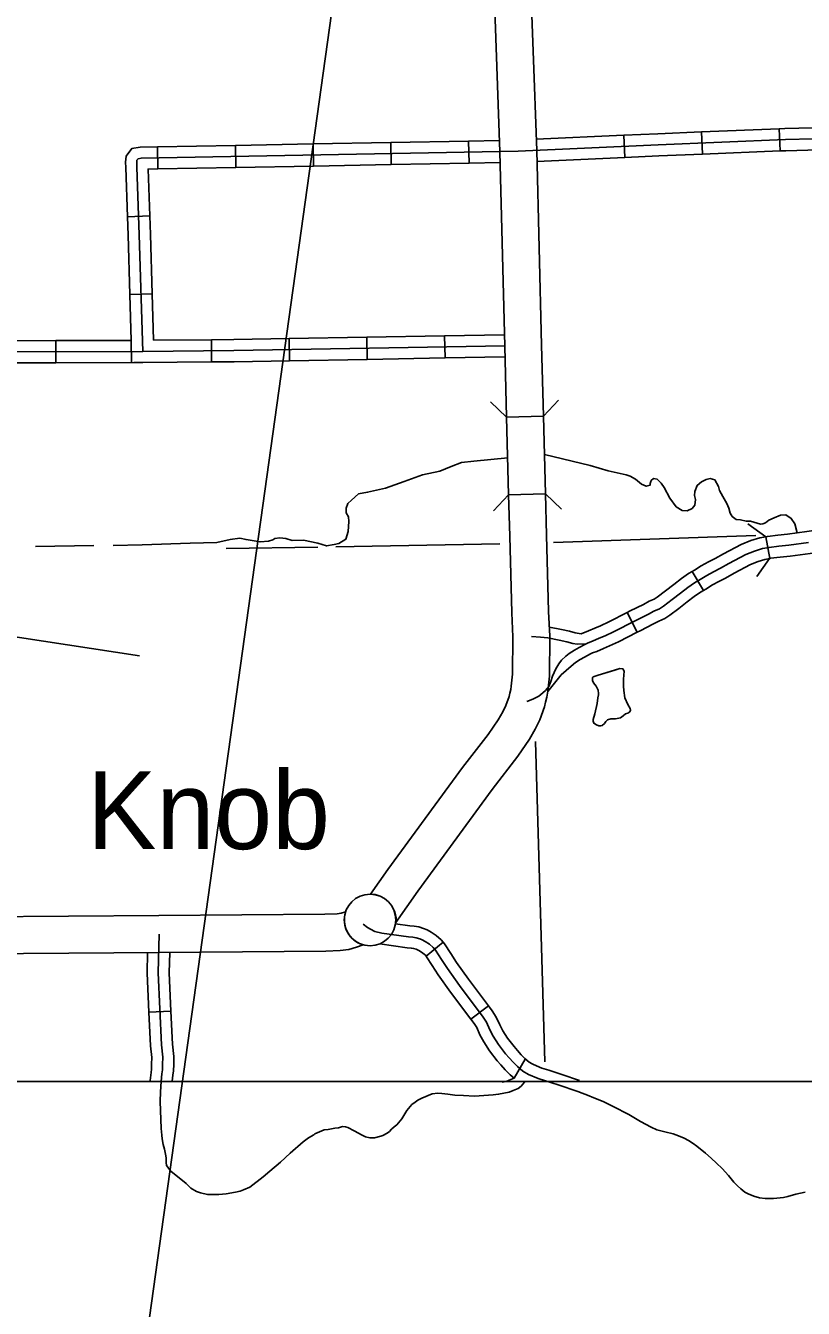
# Model space of a CAD drawing. Extents: x -5566 to 1759129, y -3726 to 731467.
# Drawn here: x -4832.8 to -4792.7, y 148.8 to 214.9 of the extents above; entities that cross this region are included whole.
import ezdxf

# ---------------------------------------------------------------- set-up
doc = ezdxf.new("R2010")
doc.units = 0
doc.layers.add('Default', color=7, linetype='Continuous')
doc.layers.add('R_No Plot', color=7, linetype='Continuous')

msp = doc.modelspace()

# ---------------------------------------------------------------- linework, layer by layer
at = {"layer": 'Default'}
for p, q in [((-4793.957, 209.609), (-4793.912, 208.471)), ((-4813.98, 208.907), (-4813.959, 207.768)), ((-4809.971, 208.982), (-4809.95, 207.843)), ((-4801.973, 209.278), (-4801.921, 208.14)), ((-4797.964, 209.449), (-4797.918, 208.31)), ((-4826.007, 208.68), (-4825.986, 207.542)), ((-4821.998, 208.756), (-4821.977, 207.617)), ((-4817.989, 208.831), (-4817.968, 207.693)), ((-4827.552, 205.078), (-4826.414, 205.118)), ((-4827.43, 201.073), (-4826.291, 201.106)), ((-4831.244, 197.558), (-4831.247, 198.697)), ((-4827.358, 197.569), (-4827.361, 198.708)), ((-4823.221, 197.598), (-4823.23, 198.737)), ((-4819.206, 197.658), (-4819.227, 198.797)), ((-4815.197, 197.729), (-4815.218, 198.868)), ((-4811.188, 197.8), (-4811.208, 198.939)), ((-4794.659, 188.587), (-4794.454, 187.466)), ((-4798.451, 186.793), (-4797.859, 185.82)), ((-4801.796, 184.688), (-4801.277, 183.674)), ((-4812.166, 166.969), (-4811.288, 167.693)), ((-4826.453, 164.078), (-4825.315, 164.129)), ((-4809.86, 163.724), (-4808.948, 164.407)), ((-4807.633, 160.687), (-4807.051, 161.666))]:
    msp.add_line(p, q, dxfattribs=at)
for points in [[(-4808.611, 250.608), (-4808.503, 248.641), (-4807.793, 238.866), (-4807.024, 228.557), (-4806.829, 218.746), (-4806.464, 208.49), (-4806.212, 198.466), (-4806.116, 194.8)], [(-4806.116, 194.8), (-4808.014, 194.75), (-4808.11, 198.417), (-4808.362, 208.432), (-4808.727, 218.693), (-4808.921, 228.467), (-4809.687, 238.726), (-4810.398, 248.52), (-4810.507, 250.505)], [(-4829.868, 123.724), (-4829.868, 123.724), (-4813.198, 243.138)], [(-4787.797, 217.644), (-4787.592, 212.789), (-4787.515, 210.186), (-4787.571, 210.105), (-4787.69, 210.011), (-4788.167, 209.811), (-4788.634, 209.538), (-4789.008, 209.375), (-4789.249, 209.291), (-4789.461, 209.239), (-4789.684, 209.188), (-4790.113, 209.159), (-4790.784, 209.13), (-4793.645, 209.052), (-4800.199, 208.789), (-4807.413, 208.461), (-4826.849, 208.095), (-4827.014, 208.066), (-4827.072, 207.988), (-4827.082, 207.881), (-4827.072, 207.637), (-4826.949, 204.144), (-4826.775, 198.14)], [(-4793.957, 209.609), (-4797.964, 209.449)], [(-4789.966, 209.74), (-4790.144, 209.728), (-4790.804, 209.699), (-4793.664, 209.621), (-4793.957, 209.609)], [(-4813.98, 208.907), (-4817.989, 208.831)], [(-4809.971, 208.982), (-4813.98, 208.907)], [(-4808.382, 209.012), (-4809.971, 208.982)], [(-4801.973, 209.278), (-4806.485, 209.073)], [(-4797.964, 209.449), (-4800.223, 209.358), (-4801.973, 209.278)], [(-4826.007, 208.68), (-4826.904, 208.664), (-4827.335, 208.588), (-4827.625, 208.2), (-4827.653, 207.895), (-4827.642, 207.616), (-4827.552, 205.078)], [(-4821.998, 208.756), (-4826.007, 208.68)], [(-4817.989, 208.831), (-4821.998, 208.756)], [(-4797.918, 208.31), (-4800.174, 208.22), (-4801.921, 208.14)], [(-4793.912, 208.471), (-4797.918, 208.31)], [(-4789.888, 208.603), (-4790.081, 208.59), (-4790.764, 208.56), (-4793.625, 208.483), (-4793.912, 208.471)], [(-4821.977, 207.617), (-4825.986, 207.542)], [(-4817.968, 207.693), (-4821.977, 207.617)], [(-4813.959, 207.768), (-4817.968, 207.693)], [(-4809.95, 207.843), (-4813.959, 207.768)], [(-4808.348, 207.874), (-4809.95, 207.843)], [(-4801.921, 208.14), (-4806.45, 207.935)], [(-4825.986, 207.542), (-4826.499, 207.532), (-4826.414, 205.118)], [(-4827.552, 205.078), (-4827.519, 204.126), (-4827.43, 201.073)], [(-4826.414, 205.118), (-4826.38, 204.162), (-4826.291, 201.106)], [(-4827.43, 201.073), (-4827.361, 198.708)], [(-4826.291, 201.106), (-4826.222, 198.714)], [(-4811.208, 198.939), (-4808.12, 198.994)], [(-4846.324, 187.972), (-4846.526, 195.499), (-4846.607, 197.275), (-4846.615, 197.587), (-4846.607, 197.735), (-4846.548, 197.839), (-4846.429, 197.906), (-4846.261, 197.925), (-4846.033, 197.944), (-4843.755, 197.958), (-4833.845, 198.12), (-4826.775, 198.14), (-4822.075, 198.177), (-4808.11, 198.424)], [(-4835.264, 198.667), (-4833.851, 198.69), (-4831.247, 198.697)], [(-4831.247, 198.697), (-4827.361, 198.708)], [(-4826.222, 198.714), (-4823.23, 198.737)], [(-4823.23, 198.737), (-4822.082, 198.746), (-4819.227, 198.797)], [(-4819.227, 198.797), (-4815.218, 198.868)], [(-4815.218, 198.868), (-4811.208, 198.939)], [(-4819.206, 197.658), (-4815.197, 197.729)], [(-4815.197, 197.729), (-4811.188, 197.8)], [(-4811.188, 197.8), (-4808.1, 197.855)], [(-4835.245, 197.528), (-4833.84, 197.551), (-4831.244, 197.558)], [(-4831.244, 197.558), (-4827.234, 197.57)], [(-4827.234, 197.57), (-4826.772, 197.571), (-4823.221, 197.598)], [(-4823.221, 197.598), (-4822.067, 197.607), (-4819.206, 197.658)], [(-4808.014, 194.75), (-4808.84, 195.535)], [(-4805.332, 195.627), (-4806.116, 194.8)], [(-4808.014, 194.75), (-4807.909, 190.743)], [(-4806.116, 194.8), (-4806.011, 190.793)], [(-4826.794, 188.163), (-4824.32, 188.261), (-4822.958, 188.288), (-4822.263, 188.441), (-4821.763, 188.511), (-4821.443, 188.441), (-4820.72, 188.316), (-4820.29, 188.358), (-4820.072, 188.433), (-4819.961, 188.499), (-4819.704, 188.527), (-4819.399, 188.496), (-4819.074, 188.4), (-4818.49, 188.414), (-4817.753, 188.261), (-4817.296, 188.11), (-4816.906, 188.191), (-4816.667, 188.242), (-4816.294, 188.455), (-4816.183, 188.858), (-4816.141, 189.373), (-4816.169, 189.609), (-4816.278, 189.815), (-4816.282, 190.064), (-4816.197, 190.304), (-4816.002, 190.471), (-4815.653, 190.795), (-4815.179, 190.879), (-4814.251, 191.089), (-4813.302, 191.432), (-4812.347, 191.778), (-4811.464, 191.973), (-4810.868, 192.215), (-4810.337, 192.409), (-4809.702, 192.478), (-4807.959, 192.66)], [(-4806.064, 192.831), (-4803.706, 192.265), (-4802.772, 191.99), (-4801.849, 191.775), (-4801.641, 191.717), (-4801.375, 191.562), (-4801.058, 191.295), (-4800.817, 191.192), (-4800.607, 191.248), (-4800.611, 191.331), (-4800.565, 191.479), (-4800.449, 191.584), (-4800.257, 191.555), (-4800.049, 191.351), (-4799.886, 191.13), (-4799.593, 190.579), (-4799.267, 190.13), (-4798.961, 189.931), (-4798.702, 189.92), (-4798.457, 190.047), (-4798.306, 190.222), (-4798.282, 190.498), (-4798.33, 190.717), (-4798.318, 190.924), (-4798.188, 191.228), (-4797.969, 191.414), (-4797.724, 191.533), (-4797.521, 191.581), (-4797.283, 191.524), (-4797.098, 191.174), (-4797.035, 190.978), (-4796.86, 190.666), (-4796.668, 190.301), (-4796.557, 190.063), (-4796.498, 189.798), (-4796.384, 189.636), (-4796.186, 189.47), (-4795.951, 189.455), (-4795.674, 189.392), (-4795.441, 189.395), (-4794.922, 189.238), (-4794.812, 189.254), (-4794.663, 189.301), (-4794.489, 189.438), (-4794.229, 189.565), (-4793.892, 189.694), (-4793.617, 189.71), (-4793.344, 189.53), (-4793.158, 189.257), (-4793.031, 188.784)], [(-4826.935, 182.452), (-4843.256, 184.94), (-4846.227, 185.456), (-4848.789, 185.805), (-4851.152, 186.181), (-4852.083, 186.359), (-4856.427, 186.982), (-4862.755, 188.176), (-4869.158, 189.202), (-4878.205, 190.691)], [(-4815.029, 170.165), (-4814.798, 170.147), (-4814.539, 170.064), (-4814.304, 169.944), (-4814.106, 169.773), (-4813.93, 169.557), (-4813.783, 169.261), (-4813.709, 168.952), (-4813.731, 168.71), (-4812.597, 170.324), (-4808.766, 175.557), (-4807.431, 177.283), (-4806.841, 178.146), (-4806.543, 178.666), (-4806.297, 179.15), (-4806.066, 179.82), (-4806.007, 180.061), (-4805.942, 180.312), (-4805.888, 180.631), (-4805.812, 181.402), (-4805.787, 183.454), (-4805.849, 184.742), (-4805.955, 188.671), (-4806.011, 190.793), (-4807.909, 190.743)], [(-4807.909, 190.743), (-4807.853, 188.62), (-4807.747, 184.67), (-4807.686, 183.42), (-4807.71, 181.508), (-4807.771, 180.881), (-4807.8, 180.708), (-4807.848, 180.526), (-4807.889, 180.356), (-4808.049, 179.893), (-4808.213, 179.569), (-4808.45, 179.156), (-4808.967, 178.401), (-4810.283, 176.698), (-4814.14, 171.43), (-4815.029, 170.165)], [(-4808.693, 189.917), (-4807.909, 190.743)], [(-4806.011, 190.793), (-4805.185, 190.009)], [(-4795.585, 189.244), (-4794.654, 188.587)], [(-4790.762, 189.316), (-4791.007, 189.258), (-4791.606, 189.074), (-4791.958, 188.94), (-4792.536, 188.849), (-4793.535, 188.717), (-4794.036, 188.668), (-4794.574, 188.602), (-4794.659, 188.587)], [(-4805.604, 188.283), (-4795.164, 188.652)], [(-4794.659, 188.587), (-4794.969, 188.53), (-4795.429, 188.385), (-4795.926, 188.191), (-4796.84, 187.7), (-4797.262, 187.462), (-4797.609, 187.285), (-4797.978, 187.088), (-4798.337, 186.862), (-4798.451, 186.793)], [(-4829.3, 188.129), (-4832.307, 188.088)], [(-4826.794, 188.163), (-4828.297, 188.143)], [(-4822.477, 187.98), (-4817.751, 188.058)], [(-4816.824, 188.074), (-4808.362, 188.215)], [(-4792.455, 188.286), (-4793.47, 188.151), (-4793.974, 188.101), (-4794.488, 188.039), (-4794.832, 187.976), (-4795.24, 187.848), (-4795.687, 187.673), (-4796.565, 187.201), (-4796.992, 186.96), (-4797.345, 186.78), (-4797.692, 186.595), (-4798.038, 186.378), (-4798.323, 186.204), (-4798.67, 185.969), (-4799.054, 185.678), (-4799.481, 185.344), (-4799.926, 185.015), (-4800.137, 184.873), (-4800.422, 184.749), (-4800.7, 184.595), (-4801.394, 184.254), (-4802.496, 183.69), (-4802.941, 183.48), (-4803.238, 183.356), (-4803.579, 183.207), (-4803.812, 183.119), (-4803.95, 183.052), (-4804.266, 182.885), (-4804.508, 182.749), (-4804.792, 182.569), (-4804.967, 182.428), (-4805.182, 182.223), (-4805.322, 182.044), (-4805.484, 181.776), (-4805.653, 181.407), (-4805.739, 181.122), (-4805.845, 180.875), (-4806.006, 180.668), (-4806.148, 180.544), (-4806.352, 180.365), (-4806.656, 180.224), (-4806.978, 180.088)], [(-4790.499, 188.208), (-4790.707, 188.158), (-4791.235, 187.996), (-4791.664, 187.832), (-4792.373, 187.722), (-4793.404, 187.585), (-4793.912, 187.535), (-4794.403, 187.475), (-4794.454, 187.466)], [(-4794.454, 187.466), (-4794.695, 187.422), (-4795.051, 187.31), (-4795.448, 187.155), (-4796.29, 186.703), (-4796.723, 186.458), (-4797.081, 186.275), (-4797.406, 186.101), (-4797.739, 185.893), (-4797.859, 185.82)], [(-4794.459, 187.465), (-4795.115, 186.534)], [(-4798.451, 186.793), (-4798.631, 186.684), (-4799.002, 186.432), (-4799.401, 186.129), (-4799.825, 185.797), (-4800.255, 185.481), (-4800.413, 185.374), (-4800.674, 185.26), (-4800.964, 185.1), (-4801.649, 184.763), (-4801.796, 184.688)], [(-4797.859, 185.82), (-4798.015, 185.725), (-4798.338, 185.506), (-4798.706, 185.227), (-4799.136, 184.89), (-4799.598, 184.55), (-4799.861, 184.372), (-4800.17, 184.238), (-4800.437, 184.09), (-4801.138, 183.745), (-4801.277, 183.674)], [(-4801.796, 184.688), (-4802.747, 184.201), (-4803.172, 184.001), (-4803.462, 183.88), (-4803.794, 183.734), (-4804.177, 183.589)], [(-4804.177, 183.589), (-4804.482, 183.64), (-4804.78, 183.724), (-4805.186, 183.809), (-4805.81, 183.934)], [(-4803.933, 183.061), (-4804.384, 183.046), (-4804.607, 183.083), (-4804.916, 183.17), (-4805.3, 183.251), (-4805.888, 183.369), (-4806.266, 183.406), (-4806.736, 183.437)], [(-4801.277, 183.674), (-4802.244, 183.179), (-4802.71, 182.959), (-4803.015, 182.832), (-4803.363, 182.68), (-4803.587, 182.595), (-4803.694, 182.544), (-4803.993, 182.385), (-4804.215, 182.26), (-4804.46, 182.105), (-4804.681, 181.914)], [(-4804.681, 181.914), (-4805.201, 181.464), (-4805.89, 180.617)], [(-4803.311, 180.277), (-4803.286, 180.445), (-4803.274, 180.5), (-4803.298, 180.686), (-4803.404, 180.878), (-4803.527, 181.064), (-4803.589, 181.175), (-4803.589, 181.25), (-4803.583, 181.33), (-4803.546, 181.374), (-4803.298, 181.448), (-4802.444, 181.708), (-4802.178, 181.788), (-4802.023, 181.776), (-4801.961, 181.652), (-4801.986, 181.25), (-4801.992, 180.891), (-4801.974, 180.661)], [(-4803.546, 181.374), (-4803.298, 181.448), (-4802.178, 181.788)], [(-4801.974, 180.661), (-4801.924, 180.284), (-4801.769, 179.943), (-4801.639, 179.732), (-4801.621, 179.646), (-4801.67, 179.571), (-4801.763, 179.491), (-4801.881, 179.46), (-4802.011, 179.361), (-4802.147, 179.249), (-4802.401, 179.206), (-4802.648, 179.2), (-4802.809, 179.144), (-4802.902, 179.057), (-4802.97, 178.965), (-4803.094, 178.859), (-4803.162, 178.841), (-4803.255, 178.841), (-4803.373, 178.89), (-4803.515, 178.977), (-4803.558, 179.082), (-4803.552, 179.163), (-4803.465, 179.454), (-4803.354, 179.986), (-4803.311, 180.277)], [(-4806.042, 161.524), (-4806.518, 178.041)], [(-4815.415, 167.558), (-4815.683, 167.665), (-4815.891, 167.803), (-4816.066, 167.974), (-4816.223, 168.205), (-4816.32, 168.431), (-4816.375, 168.721), (-4816.37, 168.998), (-4816.316, 169.252), (-4816.542, 169.184), (-4816.749, 169.158), (-4817.38, 169.132), (-4825.946, 169.059), (-4844.593, 168.924), (-4845.232, 168.921), (-4845.153, 167.023)], [(-4815.416, 168.618), (-4815.189, 168.44), (-4815.023, 168.357), (-4814.808, 168.246), (-4814.439, 168.162), (-4813.069, 167.971), (-4812.855, 167.951), (-4812.678, 167.921), (-4812.485, 167.862), (-4812.361, 167.815), (-4812.205, 167.723), (-4811.985, 167.581), (-4811.793, 167.411), (-4811.681, 167.275), (-4811.37, 166.801), (-4811.069, 166.327), (-4810.443, 165.451), (-4809.222, 163.823), (-4809.055, 163.561), (-4808.881, 163.171), (-4808.702, 162.842), (-4808.432, 162.413), (-4808.067, 161.944), (-4807.876, 161.737), (-4807.677, 161.499), (-4807.451, 161.28), (-4807.177, 161.046), (-4806.883, 160.871), (-4806.387, 160.665), (-4806.01, 160.545), (-4805.35, 160.331), (-4804.338, 159.993), (-4803.759, 159.772), (-4803.596, 159.701), (-4803.031, 159.481), (-4802.523, 159.219), (-4801.71, 158.808), (-4801.119, 158.444), (-4800.565, 158.155), (-4800.269, 158.019), (-4799.862, 157.92), (-4799.437, 157.805), (-4799.146, 157.706), (-4798.867, 157.598), (-4798.645, 157.475), (-4798.402, 157.32), (-4798.204, 157.181), (-4797.759, 156.815), (-4797.465, 156.561), (-4797.195, 156.307), (-4796.901, 156.029), (-4796.584, 155.671), (-4796.298, 155.329), (-4796.115, 155.131), (-4795.948, 154.972), (-4795.742, 154.805), (-4795.567, 154.718), (-4795.273, 154.598), (-4794.971, 154.519), (-4794.693, 154.479), (-4794.249, 154.487)], [(-4813.739, 168.64), (-4813.003, 168.537), (-4812.78, 168.516), (-4812.547, 168.477), (-4812.3, 168.401), (-4812.114, 168.33), (-4811.906, 168.208), (-4811.64, 168.036), (-4811.382, 167.808), (-4811.288, 167.693)], [(-4825.925, 168.11), (-4825.974, 166.108), (-4825.807, 162.396), (-4825.737, 161.771), (-4825.745, 161.393), (-4825.754, 161.103), (-4825.779, 160.909), (-4825.821, 160.505), (-4825.856, 159.985), (-4825.875, 159.479), (-4825.821, 158.08), (-4825.786, 157.746), (-4825.765, 157.557), (-4825.724, 157.267), (-4825.647, 157.016), (-4825.591, 156.773), (-4825.557, 156.571), (-4825.571, 156.328), (-4825.55, 156.175), (-4825.321, 155.889), (-4824.528, 155.256), (-4824.285, 155.02), (-4823.996, 154.838), (-4823.795, 154.764), (-4823.426, 154.69), (-4823.145, 154.681), (-4822.847, 154.686), (-4822.478, 154.728), (-4821.985, 154.811), (-4821.749, 154.86), (-4821.575, 154.923), (-4821.249, 155.062), (-4820.559, 155.593), (-4820.213, 155.889), (-4819.678, 156.348), (-4819.165, 156.809), (-4818.506, 157.407), (-4818.219, 157.606), (-4817.96, 157.759), (-4817.908, 157.807), (-4817.415, 158.013), (-4817.219, 158.039), (-4816.873, 158.099), (-4816.678, 158.12), (-4816.468, 158.186), (-4816.324, 158.176), (-4816.193, 158.141), (-4815.879, 157.974), (-4815.463, 157.742), (-4815.29, 157.661), (-4815.064, 157.602), (-4814.824, 157.602), (-4814.491, 157.689), (-4814.394, 157.72), (-4814.168, 157.849), (-4814.053, 157.939), (-4813.947, 158.046), (-4813.813, 158.166), (-4813.674, 158.28), (-4813.414, 158.581), (-4813.154, 159.021), (-4812.895, 159.323), (-4812.726, 159.446), (-4812.587, 159.552), (-4812.387, 159.653), (-4811.849, 159.882), (-4811.564, 159.903), (-4811.349, 159.896), (-4811.05, 159.861), (-4810.689, 159.813), (-4810.231, 159.787), (-4809.667, 159.75), (-4808.706, 159.818), (-4808.424, 159.854), (-4807.884, 159.965), (-4807.67, 160.045), (-4807.421, 160.157), (-4807.269, 160.267), (-4807.094, 160.47)], [(-4845.153, 167.023), (-4844.583, 167.025), (-4825.931, 167.161), (-4817.334, 167.234), (-4816.59, 167.264), (-4816.144, 167.321), (-4815.749, 167.44), (-4815.415, 167.558)], [(-4814.558, 167.604), (-4813.135, 167.406), (-4812.929, 167.386), (-4812.81, 167.366), (-4812.671, 167.323), (-4812.609, 167.3), (-4812.503, 167.238), (-4812.33, 167.126), (-4812.204, 167.014), (-4812.166, 166.969)], [(-4811.288, 167.693), (-4811.222, 167.613), (-4810.892, 167.11), (-4810.596, 166.646), (-4809.984, 165.787), (-4808.948, 164.407)], [(-4826.518, 167.157), (-4826.544, 166.102), (-4826.453, 164.078)], [(-4825.378, 167.166), (-4825.404, 166.114), (-4825.315, 164.129)], [(-4812.166, 166.969), (-4812.14, 166.937), (-4811.849, 166.492), (-4811.541, 166.008), (-4810.903, 165.115), (-4809.86, 163.724)], [(-4826.453, 164.078), (-4826.375, 162.352), (-4826.308, 161.745), (-4826.315, 161.408), (-4826.322, 161.148), (-4826.345, 160.975), (-4826.388, 160.554), (-4826.388, 160.554)], [(-4825.315, 164.129), (-4825.239, 162.44), (-4825.167, 161.796), (-4825.176, 161.379), (-4825.185, 161.058), (-4825.213, 160.842), (-4825.253, 160.521), (-4825.253, 160.521)], [(-4808.948, 164.407), (-4808.753, 164.147), (-4808.553, 163.831), (-4808.37, 163.424), (-4808.21, 163.129), (-4807.965, 162.74), (-4807.632, 162.313), (-4807.448, 162.113), (-4807.26, 161.887), (-4807.068, 161.702), (-4806.844, 161.51), (-4806.691, 161.42)], [(-4809.86, 163.724), (-4809.691, 163.499), (-4809.558, 163.29), (-4809.392, 162.919), (-4809.194, 162.554), (-4808.899, 162.085), (-4808.501, 161.575), (-4808.304, 161.362), (-4808.095, 161.11), (-4807.834, 160.859), (-4807.633, 160.687)], [(-4806.691, 161.42), (-4806.627, 161.381), (-4806.191, 161.2), (-4805.836, 161.088), (-4805.172, 160.872), (-4804.255, 160.566)], [(-4808.235, 160.474), (-4808.042, 160.514), (-4807.886, 160.572), (-4807.633, 160.687)], [(-4794.249, 154.487), (-4793.74, 154.535), (-4793.509, 154.585), (-4793.112, 154.696), (-4792.628, 154.813)]]:
    msp.add_lwpolyline(points, dxfattribs=at)
msp.add_circle((-4815.054, 168.837), 1.329, dxfattribs=at)
at = {"layer": 'R_No Plot'}
msp.add_lwpolyline([(-5018.988, 168.239), (-5018.988, 511.979), (-4446.603, 511.979), (-4446.603, 160.504), (-4913.433, 160.504)], dxfattribs=at)

# ---------------------------------------------------------------- texts
at = {"layer": 'Default'}
msp.add_text('Knob', height=4.0097, dxfattribs=at).set_placement((-4829.642, 172.488))

doc.saveas('drawing.dxf')
